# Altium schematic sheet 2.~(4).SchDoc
size 420 x 297 mm
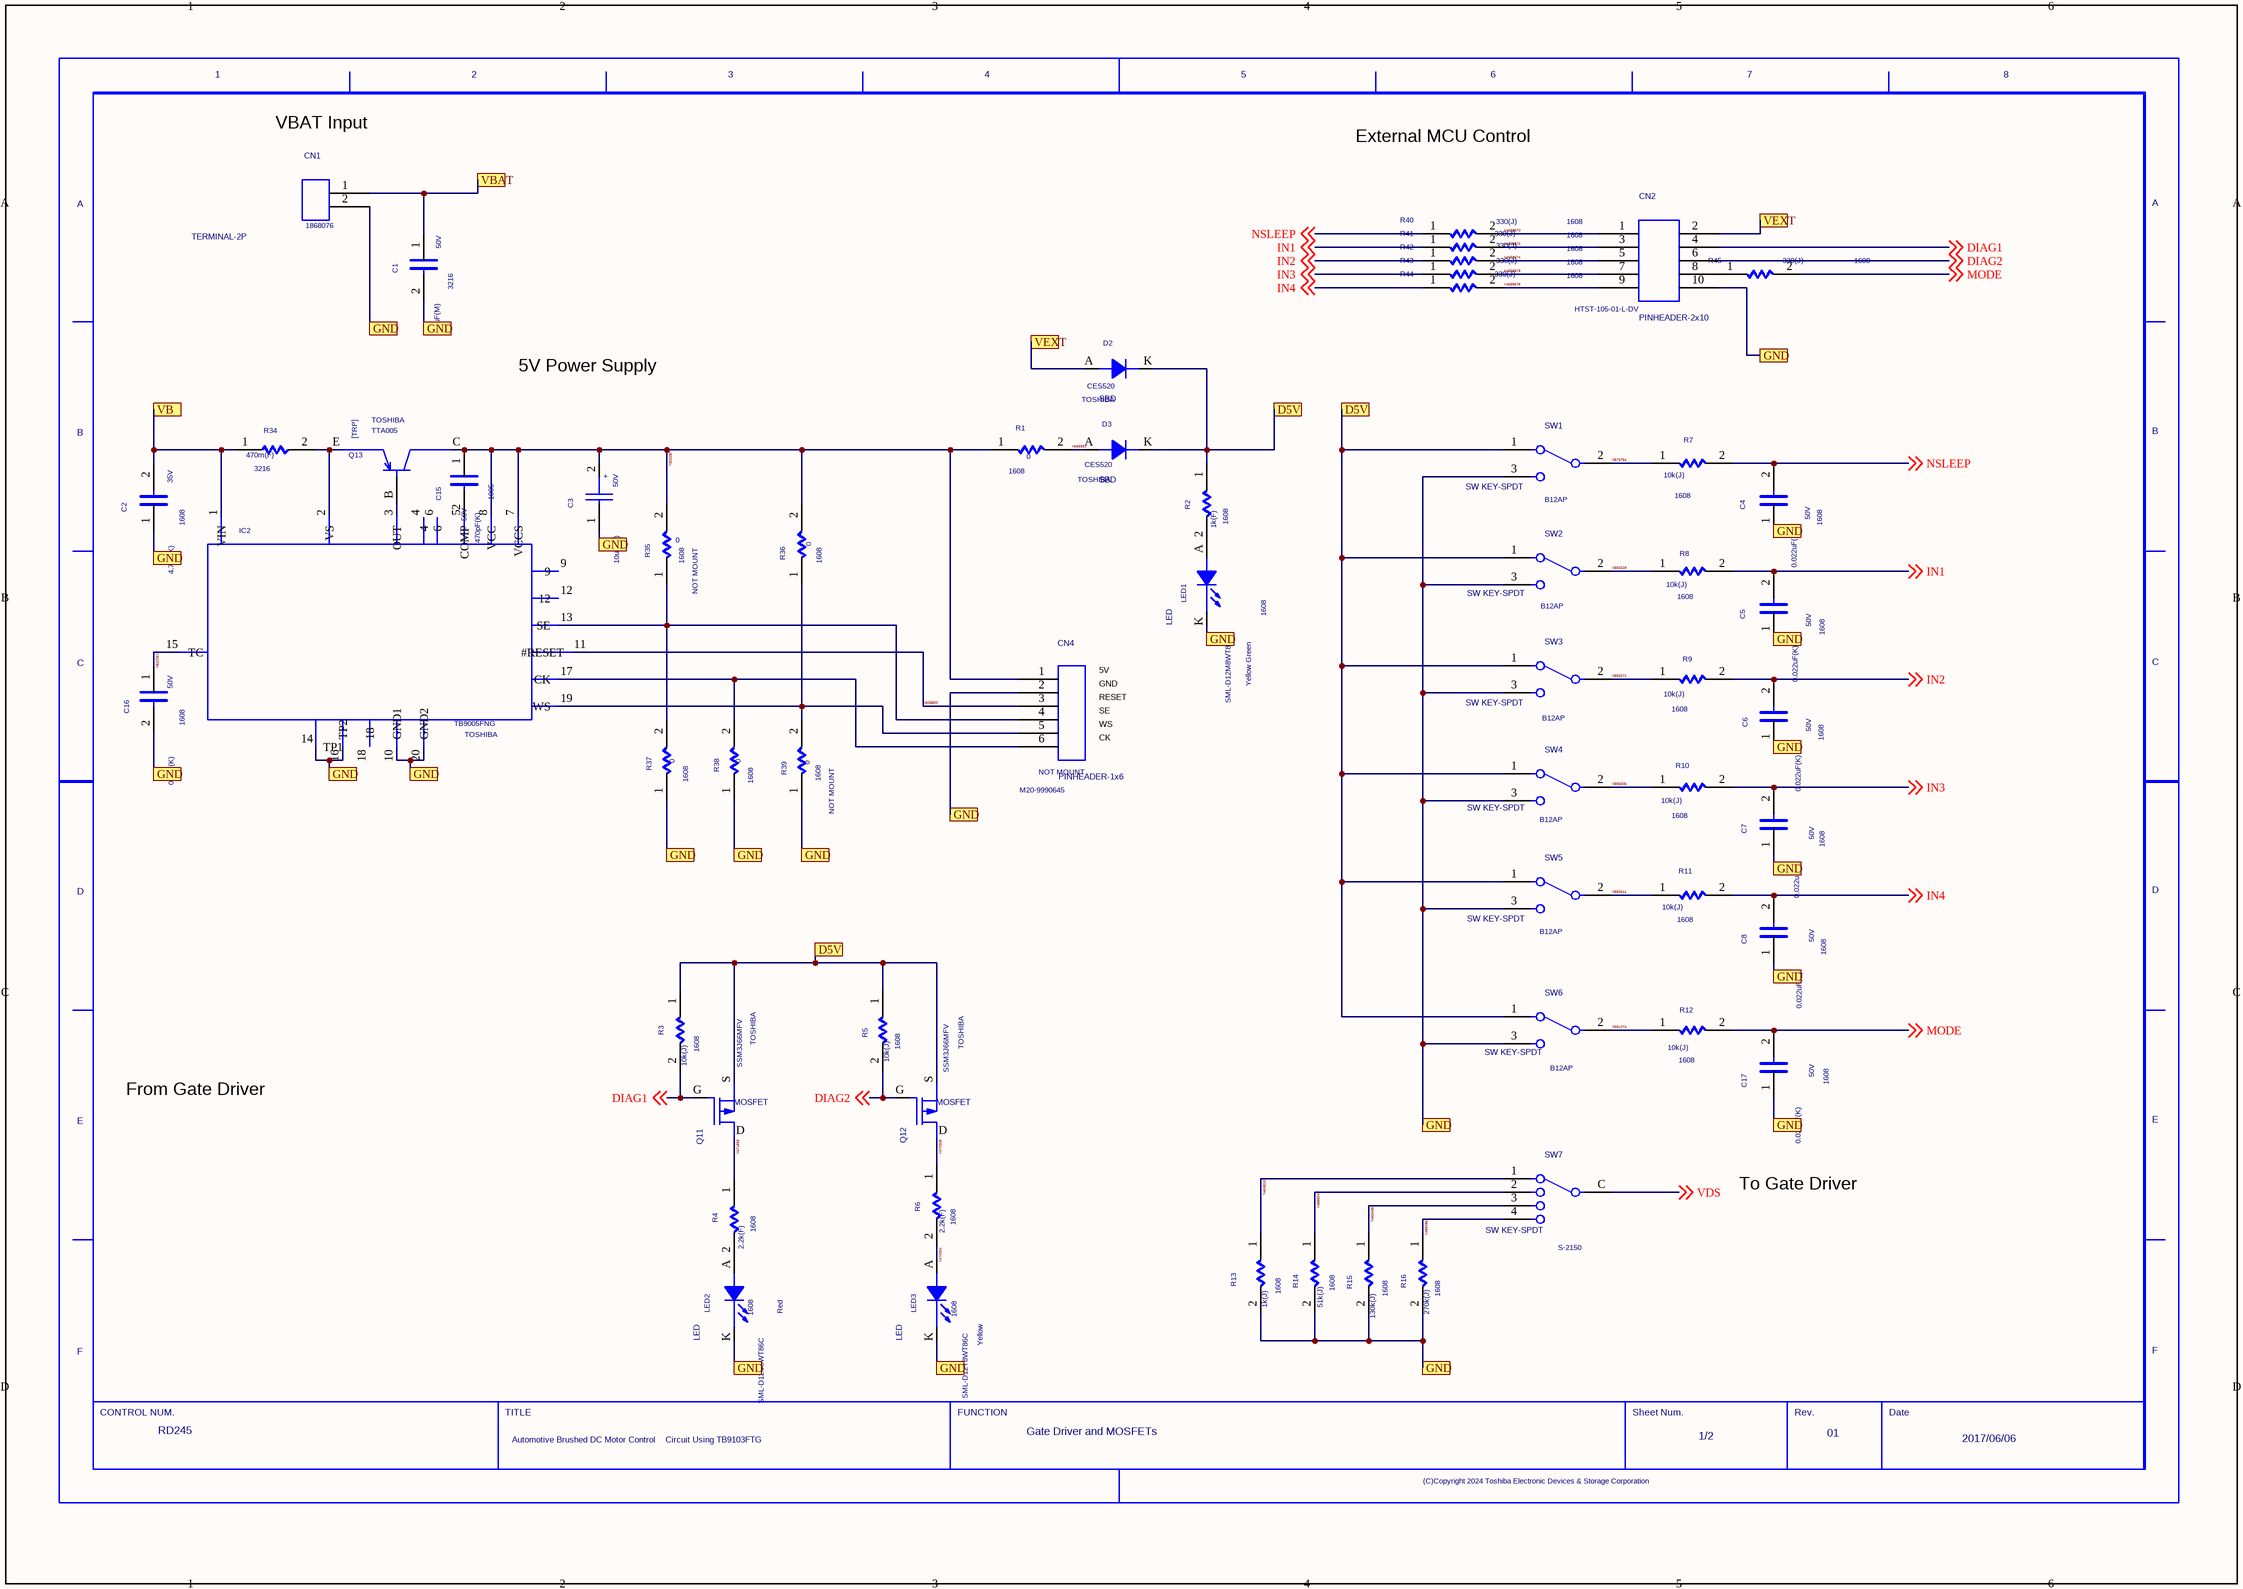
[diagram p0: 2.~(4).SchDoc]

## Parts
C1  SIZECODESMD: 3216  VAL2: 50V  VAL1: 10uF(M)  (hidden comment: C)
C2  SIZECODESMD: 1608  VAL2: 35V  VAL1: 4.7uF(K)  (hidden comment: C)
C3  VAL2: 50V  VAL1: 10uF(M)  (hidden comment: CP)
C4  SIZECODESMD: 1608  VAL2: 50V  VAL1: 0.022uF(K)  (hidden comment: C)
C5  SIZECODESMD: 1608  VAL2: 50V  VAL1: 0.022uF(K)  (hidden comment: C)
C6  SIZECODESMD: 1608  VAL2: 50V  VAL1: 0.022uF(K)  (hidden comment: C)
C7  SIZECODESMD: 1608  VAL2: 50V  VAL1: 0.022uF(K)  (hidden comment: C)
C8  SIZECODESMD: 1608  VAL2: 50V  VAL1: 0.022uF(K)  (hidden comment: C)
C15  SIZECODESMD: 1005  VAL2: 50V  VAL1: 470pF(K)  (hidden comment: C)
C16  SIZECODESMD: 1608  VAL2: 50V  VAL1: 0.1uF(K)  (hidden comment: C)
C17  SIZECODESMD: 1608  VAL2: 50V  VAL1: 0.022uF(K)  (hidden comment: C)
CN1  TERMINAL-2P  VAL3: 1868076
CN2  PINHEADER-2x10  VAL3: HTST-105-01-L-DV
CN4  PINHEADER-1x6  NOTMOUNT: NOT MOUNT  VAL3: M20-9990645
D2  SBD  USERCOMPTEXT3: TOSHIBA  VAL3: CES520
D3  SBD  USERCOMPTEXT3: TOSHIBA  VAL3: CES520
IC2  USERCOMPTEXT3: TOSHIBA  (hidden comment: TB9005FNG)
LED1  LED  SIZECODESMD: 1608  VAL3: SML-D12M8WT86C  VAL1: Yellow Green
LED2  LED  SIZECODESMD: 1608  VAL3: SML-D12U8WT86C  VAL1: Red
LED3  LED  SIZECODESMD: 1608  VAL3: SML-D12Y8WT86C  VAL1: Yellow
Q11  MOSFET  USERCOMPTEXT3: TOSHIBA  VAL3: SSM3J66MFV
Q12  MOSFET  USERCOMPTEXT3: TOSHIBA  VAL3: SSM3J66MFV
Q13  USERCOMPTEXT3: TOSHIBA  VAL3: TTA005  (hidden comment: TRP)
R1  SIZECODESMD: 1608  VAL1: 0  (hidden comment: R)
R2  SIZECODESMD: 1608  VAL1: 1k(F)  (hidden comment: R)
R3  SIZECODESMD: 1608  VAL1: 10k(J)  (hidden comment: R)
R4  SIZECODESMD: 1608  VAL1: 2.2k(F)  (hidden comment: R)
R5  SIZECODESMD: 1608  VAL1: 10k(J)  (hidden comment: R)
R6  SIZECODESMD: 1608  VAL1: 2.2k(F)  (hidden comment: R)
R7  SIZECODESMD: 1608  VAL1: 10k(J)  (hidden comment: R)
R8  SIZECODESMD: 1608  VAL1: 10k(J)  (hidden comment: R)
R9  SIZECODESMD: 1608  VAL1: 10k(J)  (hidden comment: R)
R10  SIZECODESMD: 1608  VAL1: 10k(J)  (hidden comment: R)
R11  SIZECODESMD: 1608  VAL1: 10k(J)  (hidden comment: R)
R12  SIZECODESMD: 1608  VAL1: 10k(J)  (hidden comment: R)
R13  SIZECODESMD: 1608  VAL1: 1k(J)  (hidden comment: R)
R14  SIZECODESMD: 1608  VAL1: 51k(J)  (hidden comment: R)
R15  SIZECODESMD: 1608  VAL1: 130k(J)  (hidden comment: R)
R16  SIZECODESMD: 1608  VAL1: 270k(J)  (hidden comment: R)
R34  SIZECODESMD: 3216  VAL1: 470m(F)  (hidden comment: R)
R35  SIZECODESMD: 1608  VAL1: 0  NOTMOUNT: NOT MOUNT  (hidden comment: R)
R36  SIZECODESMD: 1608  VAL1: 0  (hidden comment: R)
R37  SIZECODESMD: 1608  VAL1: 0  (hidden comment: R)
R38  SIZECODESMD: 1608  VAL1: 0  (hidden comment: R)
R39  SIZECODESMD: 1608  VAL1: 0  NOTMOUNT: NOT MOUNT  (hidden comment: R)
R40  SIZECODESMD: 1608  VAL1: 330(J)  (hidden comment: R)
R41  SIZECODESMD: 1608  VAL1: 330(J)  (hidden comment: R)
R42  SIZECODESMD: 1608  VAL1: 330(J)  (hidden comment: R)
R43  SIZECODESMD: 1608  VAL1: 330(J)  (hidden comment: R)
R44  SIZECODESMD: 1608  VAL1: 330(J)  (hidden comment: R)
R45  SIZECODESMD: 1608  VAL1: 330(J)  (hidden comment: R)
SW1  SW KEY-SPDT  VAL3: B12AP
SW2  SW KEY-SPDT  VAL3: B12AP
SW3  SW KEY-SPDT  VAL3: B12AP
SW4  SW KEY-SPDT  VAL3: B12AP
SW5  SW KEY-SPDT  VAL3: B12AP
SW6  SW KEY-SPDT  VAL3: B12AP
SW7  SW KEY-SPDT  VAL3: S-2150
U?  DATE: 2017/06/06  REVISION: 01  FUNCTION: Gate Driver and MOSFETs  DRAWINGNUMBER: RD245  TITLE: Automotive Brushed DC Motor Control / Circuit Using TB9103FTG  SHEETNUMBER: 1/2  (hidden comment: WAKU_DEF100)

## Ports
D5V, GND, VB, VBAT, VEXT

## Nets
D5V: D2.K D3.K Q11.S Q12.S R2.1 R3.1 R5.1 SW1.1(NC) SW2.1(NC) SW3.1(NC) SW4.1(NC) SW5.1(NC) SW6.1(NC) ; port D5V
DIAG1: CN2.4 Q11.G R3.2 ; off-sheet DIAG1
DIAG2: CN2.6 Q12.G R5.2 ; off-sheet DIAG2
GND: C1.2 C2.1 C3.1 C4.1 C5.1 C6.1 C7.1 C8.1 C16.2 C17.1 CN1.2 CN2.10 CN4.2 IC2.10(GND1) IC2.14(TP1) IC2.16(TP2) IC2.20(GND2) LED1.K LED2.K LED3.K R13.2 R14.2 R15.2 R16.2 R37.1 R38.1 R39.1 SW1.3(NO) SW2.3(NO) SW3.3(NO) SW4.3(NO) SW5.3(NO) SW6.3(NO) ; port GND
IN1: C5.2 R8.2 R41.1 ; off-sheet IN1
IN2: C6.2 R9.2 R42.1 ; off-sheet IN2
IN3: C7.2 R10.2 R43.1 ; off-sheet IN3
IN4: C8.2 R11.2 R44.1 ; off-sheet IN4
MODE: C17.2 R12.2 R45.2 ; off-sheet MODE
N469486: R16.1 SW7.4(NO)
N469495: R15.1 SW7.3(NO)
N469504: R14.1 SW7.2(COMMON)
N469513: R13.1 SW7.1(NC)
N470308: Q12.D R6.1
N470324: LED3.A R6.2
N471565: Q11.D R4.1
N561074: R12.1 SW6.2(COMMON)
N573754: R7.1 SW1.2(COMMON)
N593239: R8.1 SW2.2(COMMON)
N593372: R9.1 SW3.2(COMMON)
N593506: R10.1 SW4.2(COMMON)
N593641: R11.1 SW5.2(COMMON)
N622087: C3.2 C15.1 CN4.1 IC2.7(VCCS) IC2.8(VCC) Q13.C R1.1 R35.2 R36.2
N622351: C16.1 IC2.15(TC)
N628803: CN4.3 IC2.11(#RESET)
N665551: D3.A R1.2
N4658670: CN2.1 R40.2
N4658672: CN2.3 R41.2
N4658674: CN2.5 R42.2
N4658676: CN2.7 R43.2
N4658678: CN2.9 R44.2
NSLEEP: C4.2 R7.2 R40.1 ; off-sheet NSLEEP
SIG595: CN4.4 IC2.13(SE) R35.1 R37.2
SIG638: IC2.3(OUT) Q13.B
SIG639: IC2.2(VS) Q13.E R34.2
SIG642: CN4.5 IC2.19(WS) R36.1 R39.2
SIG643: CN4.6 IC2.17(CK) R38.2
VB: C2.2 IC2.1(VIN) R34.1 ; port VB
VBAT: C1.1 CN1.1 ; port VBAT
VDS: SW7.C(NO) ; off-sheet VDS
VEXT: CN2.2 D2.A ; port VEXT
NetC15_2: C15.2 IC2.5(COMP)
NetCN2_8: CN2.8 R45.1
NetLED1_A: LED1.A R2.2
NetLED2_A: LED2.A R4.2

Not connected (* = marked no-connect by the designer): IC2 4 6 9 12 18

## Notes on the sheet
- VBAT Input
- External MCU Control
- 5V Power Supply
- (near CN4) 5V
- (near CN4) GND
- (near CN4) RESET
- (near CN4) SE
- (near CN4) WS
- (near CN4) CK
- From Gate Driver
- To Gate Driver

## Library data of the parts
C1 = C: UPDATETIME: 17:22:43; UPDATEUSER: sptcae13; SAVECOUNT: 1; ORIGINALSYMBOLORIGIN: (0,0); FUNCN: C_C; VAL4: Murata; VAL3: GRT31CR61H106ME01L; CDBNAME: C0805K_2; INSTANCENAME: cmp141
C2 = C: UPDATETIME: 17:22:43; UPDATEUSER: sptcae13; SAVECOUNT: 1; ORIGINALSYMBOLORIGIN: (0,0); QUADMODEL: CON_10U; FUNCN: C_C; NOMINALCAPACITA: 10u; RATEDVOLTAGE: 25; CDMASTERCADCELG: KC0167; MAKER: TDK; OUMEMAKER: MRT 村田製作所; ADSMODELNAME: s_ZRB18AR61E106ME01L; VAL4: Murata; FNLEADFREETHET1GT2GMCTH1: N_N_N; VAL3: GRT188R6YA475KE13D; CAPACITANCETOLE: M; OUMECLASSIFICATION: セラミックコンデンサ; OUMEMAKERKATAMEI: ZRB18AR61E106ME01L; INSTANCENAME: INS669941
C3 = CP: OUMEPARTTYPE: C; SAVEAREA0: -1450,-153,20294,13055; UPDATETIME: 16:13:42; UPDATEUSER: fukuda-y; TIME: 15:02:55; SAVECOUNT: 52; ORIGINALSYMBOLORIGIN: (0,0); QUADMODEL: CON_330U; FUNCN: CP_CP; RATEDVOLTAGE: 450; NOMINALCAPACITA: 330u; CDMASTERCADCELG: DC213N; MAKER: RUBYCON; GCOUNT: 1; SIZECODESMD: DIP; OUMEMAKER: SIT ルビコン; VAL4: Chemi-Con; FNLEADFREETHET1GT2GMCTH1: 9_N_N; VAL3: HHXD500ARA100MF61G; CAPACITANCETOLE: M; OUMECLASSIFICATION: アルミ電解コンデンサ; OUMEMAKERKATAMEI: 450MXC330M35X40; CHIPSIZE: D35xL30; INSTANCENAME: INS634215
C4 = C: UPDATETIME: 17:22:43; UPDATEUSER: sptcae13; SAVECOUNT: 1; ORIGINALSYMBOLORIGIN: (0,0); QUADMODEL: CON_10U; FUNCN: C_C; NOMINALCAPACITA: 10u; RATEDVOLTAGE: 25; CDMASTERCADCELG: KC0167; MAKER: TDK; OUMEMAKER: MRT 村田製作所; ADSMODELNAME: s_ZRB18AR61E106ME01L; VAL4: Murata; FNLEADFREETHET1GT2GMCTH1: N_N_N; VAL3: GCM188R91H223KA37D; CAPACITANCETOLE: M; OUMECLASSIFICATION: セラミックコンデンサ; OUMEMAKERKATAMEI: ZRB18AR61E106ME01L; INSTANCENAME: INS573773
C5 = C: UPDATETIME: 17:22:43; UPDATEUSER: sptcae13; SAVECOUNT: 1; ORIGINALSYMBOLORIGIN: (0,0); QUADMODEL: CON_10U; FUNCN: C_C; NOMINALCAPACITA: 10u; RATEDVOLTAGE: 25; CDMASTERCADCELG: KC0167; MAKER: TDK; OUMEMAKER: MRT 村田製作所; ADSMODELNAME: s_ZRB18AR61E106ME01L; VAL4: Murata; FNLEADFREETHET1GT2GMCTH1: N_N_N; VAL3: GCM188R91H223KA37D; CAPACITANCETOLE: M; OUMECLASSIFICATION: セラミックコンデンサ; OUMEMAKERKATAMEI: ZRB18AR61E106ME01L; INSTANCENAME: INS658183
C6 = C: UPDATETIME: 17:22:43; UPDATEUSER: sptcae13; SAVECOUNT: 1; ORIGINALSYMBOLORIGIN: (0,0); QUADMODEL: CON_10U; FUNCN: C_C; NOMINALCAPACITA: 10u; RATEDVOLTAGE: 25; CDMASTERCADCELG: KC0167; MAKER: TDK; OUMEMAKER: MRT 村田製作所; ADSMODELNAME: s_ZRB18AR61E106ME01L; VAL4: Murata; FNLEADFREETHET1GT2GMCTH1: N_N_N; VAL3: GCM188R91H223KA37D; CAPACITANCETOLE: M; OUMECLASSIFICATION: セラミックコンデンサ; OUMEMAKERKATAMEI: ZRB18AR61E106ME01L; INSTANCENAME: INS658285
C7 = C: UPDATETIME: 17:22:43; UPDATEUSER: sptcae13; SAVECOUNT: 1; ORIGINALSYMBOLORIGIN: (0,0); QUADMODEL: CON_10U; FUNCN: C_C; NOMINALCAPACITA: 10u; RATEDVOLTAGE: 25; CDMASTERCADCELG: KC0167; MAKER: TDK; OUMEMAKER: MRT 村田製作所; ADSMODELNAME: s_ZRB18AR61E106ME01L; VAL4: Murata; FNLEADFREETHET1GT2GMCTH1: N_N_N; VAL3: GCM188R91H223KA37D; CAPACITANCETOLE: M; OUMECLASSIFICATION: セラミックコンデンサ; OUMEMAKERKATAMEI: ZRB18AR61E106ME01L; INSTANCENAME: INS658387
C8 = C: UPDATETIME: 17:22:43; UPDATEUSER: sptcae13; SAVECOUNT: 1; ORIGINALSYMBOLORIGIN: (0,0); QUADMODEL: CON_10U; FUNCN: C_C; NOMINALCAPACITA: 10u; RATEDVOLTAGE: 25; CDMASTERCADCELG: KC0167; MAKER: TDK; OUMEMAKER: MRT 村田製作所; ADSMODELNAME: s_ZRB18AR61E106ME01L; VAL4: Murata; FNLEADFREETHET1GT2GMCTH1: N_N_N; VAL3: GCM188R91H223KA37D; CAPACITANCETOLE: M; OUMECLASSIFICATION: セラミックコンデンサ; OUMEMAKERKATAMEI: ZRB18AR61E106ME01L; INSTANCENAME: INS658489
C15 = C: UPDATETIME: 17:22:43; UPDATEUSER: sptcae13; SAVECOUNT: 1; ORIGINALSYMBOLORIGIN: (0,0); FUNCN: C_C; VAL4: Murata; VAL3: GCM155R71H471KA37J; CDBNAME: C0805K_2; INSTANCENAME: cmp141
C16 = C: UPDATETIME: 17:22:43; UPDATEUSER: sptcae13; SAVECOUNT: 1; ORIGINALSYMBOLORIGIN: (0,0); FUNCN: C_C; VAL4: Murata; VAL3: GCM188R71H104KA57J; CDBNAME: C0805K_3; INSTANCENAME: cmp152
C17 = C: UPDATETIME: 17:22:43; UPDATEUSER: sptcae13; SAVECOUNT: 1; ORIGINALSYMBOLORIGIN: (0,0); QUADMODEL: CON_10U; FUNCN: C_C; NOMINALCAPACITA: 10u; RATEDVOLTAGE: 25; CDMASTERCADCELG: KC0167; MAKER: TDK; OUMEMAKER: MRT 村田製作所; ADSMODELNAME: s_ZRB18AR61E106ME01L; VAL4: Murata; FNLEADFREETHET1GT2GMCTH1: N_N_N; VAL3: GCM188R91H223KA37D; CAPACITANCETOLE: M; OUMECLASSIFICATION: セラミックコンデンサ; OUMEMAKERKATAMEI: ZRB18AR61E106ME01L; INSTANCENAME: INS658591
CN1 = CON2: SAVECOUNT: 1; UPDATEUSER: sptcae13; UPDATETIME: 09:49:24; OriginalSymbolOrigin: (0,0); FUNCN: CON2_CON2; VAL4: Phoenix; VAL2: 500V/32A; INSTANCENAME: INS451962
CN2 = CON10A: SAVECOUNT: 1; UPDATEUSER: sptcae13; UPDATETIME: 09:49:24; OriginalSymbolOrigin: (0,0); FUNCN: CON10A_CON10A; VAL4: Samtec; INSTANCENAME: INS465841
CN4 = CON6: SAVECOUNT: 1; UPDATEUSER: sptcae13; UPDATETIME: 09:49:24; OriginalSymbolOrigin: (0,0); FUNCN: CON6_CON6; VAL4: Harwin; INSTANCENAME: INS655764
D2 = DIODE_0: SAVECOUNT: 1; UPDATEUSER: sptcae13; UPDATETIME: 09:49:24; OriginalSymbolOrigin: (0,0); FUNCN: DIODE_0_DIODE_0; INSTANCENAME: INS572955
D3 = DIODE_0: SAVECOUNT: 1; UPDATEUSER: sptcae13; UPDATETIME: 09:49:24; OriginalSymbolOrigin: (0,0); FUNCN: DIODE_0_DIODE_0; INSTANCENAME: INS573569
IC2 = TB9005FNG_1: SAVEAREA0: -26622,-27385,86055,19754; UPDATETIME: 09:48:39; UPDATEUSER: sptcae13; TIME: 17:22:42; SAVECOUNT: 3; ORIGINALSYMBOLORIGIN: (-5080,5080); FUNCN: TB9005FNG_1_TB9005FNG_1; VAL1: LINEAR IC; INSTANCENAME: INS622199
LED1 = LED_2: SAVECOUNT: 1; UPDATEUSER: sptcae13; UPDATETIME: 09:49:24; OriginalSymbolOrigin: (0,0); FUNCN: LED_2_LED_2; VAL4: Rohm; INSTANCENAME: INS453112
LED2 = LED_2: SAVECOUNT: 1; UPDATEUSER: sptcae13; UPDATETIME: 09:49:24; OriginalSymbolOrigin: (0,0); FUNCN: LED_2_LED_2; VAL4: Rohm; INSTANCENAME: INS496113
LED3 = LED_2: SAVECOUNT: 1; UPDATEUSER: sptcae13; UPDATETIME: 09:49:24; OriginalSymbolOrigin: (0,0); FUNCN: LED_2_LED_2; VAL4: Rohm; INSTANCENAME: INS496225
Q11 = ZVP0545_TO_0: SAVECOUNT: 1; UPDATEUSER: sptcae13; UPDATETIME: 09:49:23; OriginalSymbolOrigin: (0,5080); FUNCN: ZVP0545_TO_0_ZVP0545_TO_0; INSTANCENAME: INS493920
Q12 = ZVP0545_TO_0: SAVECOUNT: 1; UPDATEUSER: sptcae13; UPDATETIME: 09:49:23; OriginalSymbolOrigin: (0,5080); FUNCN: ZVP0545_TO_0_ZVP0545_TO_0; INSTANCENAME: INS494083
Q13 = TRP: SAVEAREA0: -5466,-244,29263,20886; UPDATETIME: 17:22:43; UPDATEUSER: sptcae13; SAVECOUNT: 1; ORIGINALSYMBOLORIGIN: (0,0); FUNCN: TRP_TRP; INSTANCENAME: cmp138
R1 = R: UPDATETIME: 17:22:43; UPDATEUSER: sptcae13; SAVECOUNT: 1; ORIGINALSYMBOLORIGIN: (0,0); QUADMODEL: RES_1M; FUNCN: R_R; CDMASTERCADCELG: KC0020; MAKER: KOA; RESISTANCETOLER: J; OUMEMAKER: SSM 進工業; POWERRATING: 500m; MOUNTINGFORMSMD: SMD; NOMINALRESISTAN: 1m; ADSMODELNAME: s_RL1632H_R001_JN; FNLEADFREETHET1GT2GMCTH1: N_N_N; VAL3: RK73Z1JTTD; OUMECLASSIFICATION: 表面実装用固定抵抗器; OUMEMAKERKATAMEI: RL1632H-R001-JN; CHIPSIZE: 3216; INSTANCENAME: INS575096
R2 = R: UPDATETIME: 17:22:43; UPDATEUSER: sptcae13; SAVECOUNT: 1; ORIGINALSYMBOLORIGIN: (0,0); QUADMODEL: RES_1M; FUNCN: R_R; CDMASTERCADCELG: KC0020; MAKER: KOA; RESISTANCETOLER: J; OUMEMAKER: SSM 進工業; POWERRATING: 500m; MOUNTINGFORMSMD: SMD; NOMINALRESISTAN: 1m; ADSMODELNAME: s_RL1632H_R001_JN; FNLEADFREETHET1GT2GMCTH1: N_N_N; VAL3: RK73H1JTTD1001F; VAL2: 125mW; OUMECLASSIFICATION: 表面実装用固定抵抗器; OUMEMAKERKATAMEI: RL1632H-R001-JN; CHIPSIZE: 3216; INSTANCENAME: INS454341
R3 = R: UPDATETIME: 17:22:43; UPDATEUSER: sptcae13; SAVECOUNT: 1; ORIGINALSYMBOLORIGIN: (0,0); QUADMODEL: RES_1M; FUNCN: R_R; CDMASTERCADCELG: KC0020; MAKER: KOA; RESISTANCETOLER: J; OUMEMAKER: SSM 進工業; POWERRATING: 500m; MOUNTINGFORMSMD: SMD; NOMINALRESISTAN: 1m; ADSMODELNAME: s_RL1632H_R001_JN; FNLEADFREETHET1GT2GMCTH1: N_N_N; VAL3: RK73B1JTTD103J; VAL2: 100mW; OUMECLASSIFICATION: 表面実装用固定抵抗器; OUMEMAKERKATAMEI: RL1632H-R001-JN; CHIPSIZE: 3216; INSTANCENAME: INS486568
R4 = R: UPDATETIME: 17:22:43; UPDATEUSER: sptcae13; SAVECOUNT: 1; ORIGINALSYMBOLORIGIN: (0,0); QUADMODEL: RES_1M; FUNCN: R_R; CDMASTERCADCELG: KC0020; MAKER: KOA; RESISTANCETOLER: J; OUMEMAKER: SSM 進工業; POWERRATING: 500m; MOUNTINGFORMSMD: SMD; NOMINALRESISTAN: 1m; ADSMODELNAME: s_RL1632H_R001_JN; FNLEADFREETHET1GT2GMCTH1: N_N_N; VAL3: RK73H1JTTD2201F; VAL2: 100mW; OUMECLASSIFICATION: 表面実装用固定抵抗器; OUMEMAKERKATAMEI: RL1632H-R001-JN; CHIPSIZE: 3216; INSTANCENAME: INS471567
R5 = R: UPDATETIME: 17:22:43; UPDATEUSER: sptcae13; SAVECOUNT: 1; ORIGINALSYMBOLORIGIN: (0,0); QUADMODEL: RES_1M; FUNCN: R_R; CDMASTERCADCELG: KC0020; MAKER: KOA; RESISTANCETOLER: J; OUMEMAKER: SSM 進工業; POWERRATING: 500m; MOUNTINGFORMSMD: SMD; NOMINALRESISTAN: 1m; ADSMODELNAME: s_RL1632H_R001_JN; FNLEADFREETHET1GT2GMCTH1: N_N_N; VAL3: RK73B1JTTD103J; VAL2: 100mW; OUMECLASSIFICATION: 表面実装用固定抵抗器; OUMEMAKERKATAMEI: RL1632H-R001-JN; CHIPSIZE: 3216; INSTANCENAME: INS487189
R6 = R: UPDATETIME: 17:22:43; UPDATEUSER: sptcae13; SAVECOUNT: 1; ORIGINALSYMBOLORIGIN: (0,0); QUADMODEL: RES_1M; FUNCN: R_R; CDMASTERCADCELG: KC0020; MAKER: KOA; RESISTANCETOLER: J; OUMEMAKER: SSM 進工業; POWERRATING: 500m; MOUNTINGFORMSMD: SMD; NOMINALRESISTAN: 1m; ADSMODELNAME: s_RL1632H_R001_JN; FNLEADFREETHET1GT2GMCTH1: N_N_N; VAL3: RK73H1JTTD2201F; VAL2: 100mW; OUMECLASSIFICATION: 表面実装用固定抵抗器; OUMEMAKERKATAMEI: RL1632H-R001-JN; CHIPSIZE: 3216; INSTANCENAME: INS470310
R7 = R: UPDATETIME: 17:22:43; UPDATEUSER: sptcae13; SAVECOUNT: 1; ORIGINALSYMBOLORIGIN: (0,0); QUADMODEL: RES_1M; FUNCN: R_R; CDMASTERCADCELG: KC0020; MAKER: KOA; RESISTANCETOLER: J; OUMEMAKER: SSM 進工業; POWERRATING: 500m; MOUNTINGFORMSMD: SMD; NOMINALRESISTAN: 1m; ADSMODELNAME: s_RL1632H_R001_JN; FNLEADFREETHET1GT2GMCTH1: N_N_N; VAL3: RK73B1JTTD103J; VAL2: 100mW; OUMECLASSIFICATION: 表面実装用固定抵抗器; OUMEMAKERKATAMEI: RL1632H-R001-JN; CHIPSIZE: 3216; INSTANCENAME: INS515728
R8 = R: UPDATETIME: 17:22:43; UPDATEUSER: sptcae13; SAVECOUNT: 1; ORIGINALSYMBOLORIGIN: (0,0); QUADMODEL: RES_1M; FUNCN: R_R; CDMASTERCADCELG: KC0020; MAKER: KOA; RESISTANCETOLER: J; OUMEMAKER: SSM 進工業; POWERRATING: 500m; MOUNTINGFORMSMD: SMD; NOMINALRESISTAN: 1m; ADSMODELNAME: s_RL1632H_R001_JN; FNLEADFREETHET1GT2GMCTH1: N_N_N; VAL3: RK73B1JTTD103J; VAL2: 100mW; OUMECLASSIFICATION: 表面実装用固定抵抗器; OUMEMAKERKATAMEI: RL1632H-R001-JN; CHIPSIZE: 3216; INSTANCENAME: INS593225
R9 = R: UPDATETIME: 17:22:43; UPDATEUSER: sptcae13; SAVECOUNT: 1; ORIGINALSYMBOLORIGIN: (0,0); QUADMODEL: RES_1M; FUNCN: R_R; CDMASTERCADCELG: KC0020; MAKER: KOA; RESISTANCETOLER: J; OUMEMAKER: SSM 進工業; POWERRATING: 500m; MOUNTINGFORMSMD: SMD; NOMINALRESISTAN: 1m; ADSMODELNAME: s_RL1632H_R001_JN; FNLEADFREETHET1GT2GMCTH1: N_N_N; VAL3: RK73B1JTTD103J; VAL2: 100mW; OUMECLASSIFICATION: 表面実装用固定抵抗器; OUMEMAKERKATAMEI: RL1632H-R001-JN; CHIPSIZE: 3216; INSTANCENAME: INS593358
R10 = R: UPDATETIME: 17:22:43; UPDATEUSER: sptcae13; SAVECOUNT: 1; ORIGINALSYMBOLORIGIN: (0,0); QUADMODEL: RES_1M; FUNCN: R_R; CDMASTERCADCELG: KC0020; MAKER: KOA; RESISTANCETOLER: J; OUMEMAKER: SSM 進工業; POWERRATING: 500m; MOUNTINGFORMSMD: SMD; NOMINALRESISTAN: 1m; ADSMODELNAME: s_RL1632H_R001_JN; FNLEADFREETHET1GT2GMCTH1: N_N_N; VAL3: RK73B1JTTD103J; VAL2: 100mW; OUMECLASSIFICATION: 表面実装用固定抵抗器; OUMEMAKERKATAMEI: RL1632H-R001-JN; CHIPSIZE: 3216; INSTANCENAME: INS593492
R11 = R: UPDATETIME: 17:22:43; UPDATEUSER: sptcae13; SAVECOUNT: 1; ORIGINALSYMBOLORIGIN: (0,0); QUADMODEL: RES_1M; FUNCN: R_R; CDMASTERCADCELG: KC0020; MAKER: KOA; RESISTANCETOLER: J; OUMEMAKER: SSM 進工業; POWERRATING: 500m; MOUNTINGFORMSMD: SMD; NOMINALRESISTAN: 1m; ADSMODELNAME: s_RL1632H_R001_JN; FNLEADFREETHET1GT2GMCTH1: N_N_N; VAL3: RK73B1JTTD103J; VAL2: 100mW; OUMECLASSIFICATION: 表面実装用固定抵抗器; OUMEMAKERKATAMEI: RL1632H-R001-JN; CHIPSIZE: 3216; INSTANCENAME: INS593627
R12 = R: UPDATETIME: 17:22:43; UPDATEUSER: sptcae13; SAVECOUNT: 1; ORIGINALSYMBOLORIGIN: (0,0); QUADMODEL: RES_1M; FUNCN: R_R; CDMASTERCADCELG: KC0020; MAKER: KOA; RESISTANCETOLER: J; OUMEMAKER: SSM 進工業; POWERRATING: 500m; MOUNTINGFORMSMD: SMD; NOMINALRESISTAN: 1m; ADSMODELNAME: s_RL1632H_R001_JN; FNLEADFREETHET1GT2GMCTH1: N_N_N; VAL3: RK73B1JTTD103J; VAL2: 100mW; OUMECLASSIFICATION: 表面実装用固定抵抗器; OUMEMAKERKATAMEI: RL1632H-R001-JN; CHIPSIZE: 3216; INSTANCENAME: INS561051
R13 = R: UPDATETIME: 17:22:43; UPDATEUSER: sptcae13; SAVECOUNT: 1; ORIGINALSYMBOLORIGIN: (0,0); QUADMODEL: RES_1M; FUNCN: R_R; CDMASTERCADCELG: KC0020; MAKER: KOA; RESISTANCETOLER: J; OUMEMAKER: SSM 進工業; POWERRATING: 500m; MOUNTINGFORMSMD: SMD; NOMINALRESISTAN: 1m; ADSMODELNAME: s_RL1632H_R001_JN; FNLEADFREETHET1GT2GMCTH1: N_N_N; VAL3: RK73B1JTTD102J; VAL2: 125mW; OUMECLASSIFICATION: 表面実装用固定抵抗器; OUMEMAKERKATAMEI: RL1632H-R001-JN; CHIPSIZE: 3216; INSTANCENAME: INS467908
R14 = R: UPDATETIME: 17:22:43; UPDATEUSER: sptcae13; SAVECOUNT: 1; ORIGINALSYMBOLORIGIN: (0,0); QUADMODEL: RES_1M; FUNCN: R_R; CDMASTERCADCELG: KC0020; MAKER: KOA; RESISTANCETOLER: J; OUMEMAKER: SSM 進工業; POWERRATING: 500m; MOUNTINGFORMSMD: SMD; NOMINALRESISTAN: 1m; ADSMODELNAME: s_RL1632H_R001_JN; FNLEADFREETHET1GT2GMCTH1: N_N_N; VAL3: RK73B1JTTD513J; VAL2: 100mW; OUMECLASSIFICATION: 表面実装用固定抵抗器; OUMEMAKERKATAMEI: RL1632H-R001-JN; CHIPSIZE: 3216; INSTANCENAME: INS467930
R15 = R: UPDATETIME: 17:22:43; UPDATEUSER: sptcae13; SAVECOUNT: 1; ORIGINALSYMBOLORIGIN: (0,0); QUADMODEL: RES_1M; FUNCN: R_R; CDMASTERCADCELG: KC0020; MAKER: KOA; RESISTANCETOLER: J; OUMEMAKER: SSM 進工業; POWERRATING: 500m; MOUNTINGFORMSMD: SMD; NOMINALRESISTAN: 1m; ADSMODELNAME: s_RL1632H_R001_JN; FNLEADFREETHET1GT2GMCTH1: N_N_N; VAL3: RK73B1JTTD134J; VAL2: 100mW; OUMECLASSIFICATION: 表面実装用固定抵抗器; OUMEMAKERKATAMEI: RL1632H-R001-JN; CHIPSIZE: 3216; INSTANCENAME: INS467952
R16 = R: UPDATETIME: 17:22:43; UPDATEUSER: sptcae13; SAVECOUNT: 1; ORIGINALSYMBOLORIGIN: (0,0); QUADMODEL: RES_1M; FUNCN: R_R; CDMASTERCADCELG: KC0020; MAKER: KOA; RESISTANCETOLER: J; OUMEMAKER: SSM 進工業; POWERRATING: 500m; MOUNTINGFORMSMD: SMD; NOMINALRESISTAN: 1m; ADSMODELNAME: s_RL1632H_R001_JN; FNLEADFREETHET1GT2GMCTH1: N_N_N; VAL3: RK73B1JTTD274J; VAL2: 100mW; OUMECLASSIFICATION: 表面実装用固定抵抗器; OUMEMAKERKATAMEI: RL1632H-R001-JN; CHIPSIZE: 3216; INSTANCENAME: INS467974
R34 = R: UPDATETIME: 17:22:43; UPDATEUSER: sptcae13; SAVECOUNT: 1; ORIGINALSYMBOLORIGIN: (0,0); FUNCN: R_R; VAL4: Panasonic; VAL3: ERJ8BQFR47V; VAL2: 0.5W; CDBNAME: R1206; INSTANCENAME: cmp140
R35 = R: UPDATETIME: 17:22:43; UPDATEUSER: sptcae13; SAVECOUNT: 1; ORIGINALSYMBOLORIGIN: (0,0); QUADMODEL: RES_1M; FUNCN: R_R; CDMASTERCADCELG: KC0020; MAKER: KOA; RESISTANCETOLER: J; OUMEMAKER: SSM 進工業; POWERRATING: 500m; MOUNTINGFORMSMD: SMD; NOMINALRESISTAN: 1m; ADSMODELNAME: s_RL1632H_R001_JN; FNLEADFREETHET1GT2GMCTH1: N_N_N; VAL3: RK73Z1JTTD; OUMECLASSIFICATION: 表面実装用固定抵抗器; OUMEMAKERKATAMEI: RL1632H-R001-JN; CHIPSIZE: 3216; INSTANCENAME: INS628941
R36 = R: UPDATETIME: 17:22:43; UPDATEUSER: sptcae13; SAVECOUNT: 1; ORIGINALSYMBOLORIGIN: (0,0); QUADMODEL: RES_1M; FUNCN: R_R; CDMASTERCADCELG: KC0020; MAKER: KOA; RESISTANCETOLER: J; OUMEMAKER: SSM 進工業; POWERRATING: 500m; MOUNTINGFORMSMD: SMD; NOMINALRESISTAN: 1m; ADSMODELNAME: s_RL1632H_R001_JN; FNLEADFREETHET1GT2GMCTH1: N_N_N; VAL3: RK73Z1JTTD; OUMECLASSIFICATION: 表面実装用固定抵抗器; OUMEMAKERKATAMEI: RL1632H-R001-JN; CHIPSIZE: 3216; INSTANCENAME: INS628993
R37 = R: UPDATETIME: 17:22:43; UPDATEUSER: sptcae13; SAVECOUNT: 1; ORIGINALSYMBOLORIGIN: (0,0); QUADMODEL: RES_1M; FUNCN: R_R; CDMASTERCADCELG: KC0020; MAKER: KOA; RESISTANCETOLER: J; OUMEMAKER: SSM 進工業; POWERRATING: 500m; MOUNTINGFORMSMD: SMD; NOMINALRESISTAN: 1m; ADSMODELNAME: s_RL1632H_R001_JN; FNLEADFREETHET1GT2GMCTH1: N_N_N; VAL3: RK73Z1JTTD; OUMECLASSIFICATION: 表面実装用固定抵抗器; OUMEMAKERKATAMEI: RL1632H-R001-JN; CHIPSIZE: 3216; INSTANCENAME: INS629194
R38 = R: UPDATETIME: 17:22:43; UPDATEUSER: sptcae13; SAVECOUNT: 1; ORIGINALSYMBOLORIGIN: (0,0); QUADMODEL: RES_1M; FUNCN: R_R; CDMASTERCADCELG: KC0020; MAKER: KOA; RESISTANCETOLER: J; OUMEMAKER: SSM 進工業; POWERRATING: 500m; MOUNTINGFORMSMD: SMD; NOMINALRESISTAN: 1m; ADSMODELNAME: s_RL1632H_R001_JN; FNLEADFREETHET1GT2GMCTH1: N_N_N; VAL3: RK73Z1JTTD; OUMECLASSIFICATION: 表面実装用固定抵抗器; OUMEMAKERKATAMEI: RL1632H-R001-JN; CHIPSIZE: 3216; INSTANCENAME: INS629216
R39 = R: UPDATETIME: 17:22:43; UPDATEUSER: sptcae13; SAVECOUNT: 1; ORIGINALSYMBOLORIGIN: (0,0); QUADMODEL: RES_1M; FUNCN: R_R; CDMASTERCADCELG: KC0020; MAKER: KOA; RESISTANCETOLER: J; OUMEMAKER: SSM 進工業; POWERRATING: 500m; MOUNTINGFORMSMD: SMD; NOMINALRESISTAN: 1m; ADSMODELNAME: s_RL1632H_R001_JN; FNLEADFREETHET1GT2GMCTH1: N_N_N; VAL3: RK73Z1JTTD; OUMECLASSIFICATION: 表面実装用固定抵抗器; OUMEMAKERKATAMEI: RL1632H-R001-JN; CHIPSIZE: 3216; INSTANCENAME: INS634861
R40 = R_0: SAVECOUNT: 1; UPDATEUSER: sptcae13; UPDATETIME: 09:49:24; ORIGINALSYMBOLORIGIN: (0,0); QUADMODEL: RES_1M; FUNCN: R_0_R_0; CDMASTERCADCELG: KC0020; MAKER: KOA; RESISTANCETOLER: J; OUMEMAKER: SSM 進工業; POWERRATING: 500m; MOUNTINGFORMSMD: SMD; NOMINALRESISTAN: 1m; ADSMODELNAME: s_RL1632H_R001_JN; FNLEADFREETHET1GT2GMCTH1: N_N_N; VAL3: RK73B1JTTD331J; VAL2: 125mW; OUMECLASSIFICATION: 表面実装用固定抵抗器; OUMEMAKERKATAMEI: RL1632H-R001-JN; CHIPSIZE: 3216; INSTANCENAME: INS642505
R41 = R_0: SAVECOUNT: 1; UPDATEUSER: sptcae13; UPDATETIME: 09:49:24; ORIGINALSYMBOLORIGIN: (0,0); QUADMODEL: RES_1M; FUNCN: R_0_R_0; CDMASTERCADCELG: KC0020; MAKER: KOA; RESISTANCETOLER: J; OUMEMAKER: SSM 進工業; POWERRATING: 500m; MOUNTINGFORMSMD: SMD; NOMINALRESISTAN: 1m; ADSMODELNAME: s_RL1632H_R001_JN; FNLEADFREETHET1GT2GMCTH1: N_N_N; VAL3: RK73B1JTTD331J; VAL2: 125mW; OUMECLASSIFICATION: 表面実装用固定抵抗器; OUMEMAKERKATAMEI: RL1632H-R001-JN; CHIPSIZE: 3216; INSTANCENAME: INS642429
R42 = R_0: SAVECOUNT: 1; UPDATEUSER: sptcae13; UPDATETIME: 09:49:24; ORIGINALSYMBOLORIGIN: (0,0); QUADMODEL: RES_1M; FUNCN: R_0_R_0; CDMASTERCADCELG: KC0020; MAKER: KOA; RESISTANCETOLER: J; OUMEMAKER: SSM 進工業; POWERRATING: 500m; MOUNTINGFORMSMD: SMD; NOMINALRESISTAN: 1m; ADSMODELNAME: s_RL1632H_R001_JN; FNLEADFREETHET1GT2GMCTH1: N_N_N; VAL3: RK73B1JTTD331J; VAL2: 125mW; OUMECLASSIFICATION: 表面実装用固定抵抗器; OUMEMAKERKATAMEI: RL1632H-R001-JN; CHIPSIZE: 3216; INSTANCENAME: INS642303
R43 = R_0: SAVECOUNT: 1; UPDATEUSER: sptcae13; UPDATETIME: 09:49:24; ORIGINALSYMBOLORIGIN: (0,0); QUADMODEL: RES_1M; FUNCN: R_0_R_0; CDMASTERCADCELG: KC0020; MAKER: KOA; RESISTANCETOLER: J; OUMEMAKER: SSM 進工業; POWERRATING: 500m; MOUNTINGFORMSMD: SMD; NOMINALRESISTAN: 1m; ADSMODELNAME: s_RL1632H_R001_JN; FNLEADFREETHET1GT2GMCTH1: N_N_N; VAL3: RK73B1JTTD331J; VAL2: 125mW; OUMECLASSIFICATION: 表面実装用固定抵抗器; OUMEMAKERKATAMEI: RL1632H-R001-JN; CHIPSIZE: 3216; INSTANCENAME: INS642261
R44 = R_0: SAVECOUNT: 1; UPDATEUSER: sptcae13; UPDATETIME: 09:49:24; ORIGINALSYMBOLORIGIN: (0,0); QUADMODEL: RES_1M; FUNCN: R_0_R_0; CDMASTERCADCELG: KC0020; MAKER: KOA; RESISTANCETOLER: J; OUMEMAKER: SSM 進工業; POWERRATING: 500m; MOUNTINGFORMSMD: SMD; NOMINALRESISTAN: 1m; ADSMODELNAME: s_RL1632H_R001_JN; FNLEADFREETHET1GT2GMCTH1: N_N_N; VAL3: RK73B1JTTD331J; VAL2: 125mW; OUMECLASSIFICATION: 表面実装用固定抵抗器; OUMEMAKERKATAMEI: RL1632H-R001-JN; CHIPSIZE: 3216; INSTANCENAME: INS642387
R45 = R_0: SAVECOUNT: 1; UPDATEUSER: sptcae13; UPDATETIME: 09:49:24; ORIGINALSYMBOLORIGIN: (0,0); QUADMODEL: RES_1M; FUNCN: R_0_R_0; CDMASTERCADCELG: KC0020; MAKER: KOA; RESISTANCETOLER: J; OUMEMAKER: SSM 進工業; POWERRATING: 500m; MOUNTINGFORMSMD: SMD; NOMINALRESISTAN: 1m; ADSMODELNAME: s_RL1632H_R001_JN; FNLEADFREETHET1GT2GMCTH1: N_N_N; VAL3: RK73B1JTTD331J; VAL2: 125mW; OUMECLASSIFICATION: 表面実装用固定抵抗器; OUMEMAKERKATAMEI: RL1632H-R001-JN; CHIPSIZE: 3216; INSTANCENAME: INS642773
SW1 = 154ANS_0: SAVECOUNT: 1; UPDATEUSER: sptcae13; UPDATETIME: 09:49:24; OriginalSymbolOrigin: (-2540,0); FUNCN: 154ANS_0_154ANS_0; VAL4: NKK; VAL2: 28VDC/0.4VA; INSTANCENAME: INS614366
SW2 = 154ANS_0: SAVECOUNT: 1; UPDATEUSER: sptcae13; UPDATETIME: 09:49:24; OriginalSymbolOrigin: (-2540,0); FUNCN: 154ANS_0_154ANS_0; VAL4: NKK; VAL2: 28VDC/0.4VA; INSTANCENAME: INS473874
SW3 = 154ANS_0: SAVECOUNT: 1; UPDATEUSER: sptcae13; UPDATETIME: 09:49:24; OriginalSymbolOrigin: (-2540,0); FUNCN: 154ANS_0_154ANS_0; VAL4: NKK; VAL2: 28VDC/0.4VA; INSTANCENAME: INS614843
SW4 = 154ANS_0: SAVECOUNT: 1; UPDATEUSER: sptcae13; UPDATETIME: 09:49:24; OriginalSymbolOrigin: (-2540,0); FUNCN: 154ANS_0_154ANS_0; VAL4: NKK; VAL2: 28VDC/0.4VA; INSTANCENAME: INS614962
SW5 = 154ANS_0: SAVECOUNT: 1; UPDATEUSER: sptcae13; UPDATETIME: 09:49:24; OriginalSymbolOrigin: (-2540,0); FUNCN: 154ANS_0_154ANS_0; VAL4: NKK; VAL2: 28VDC/0.4VA; INSTANCENAME: INS615081
SW6 = 154ANS_0: SAVECOUNT: 1; UPDATEUSER: sptcae13; UPDATETIME: 09:49:24; OriginalSymbolOrigin: (-2540,0); FUNCN: 154ANS_0_154ANS_0; VAL4: NKK; VAL2: 28VDC/0.4VA; INSTANCENAME: INS615857
SW7 = 154ANS_2: SAVECOUNT: 1; UPDATEUSER: sptcae13; UPDATETIME: 09:49:24; OriginalSymbolOrigin: (-2540,0); FUNCN: 154ANS_2_154ANS_2; VAL4: Nidec Copal; INSTANCENAME: INS469431
U? = WAKU_DEF100_1: SAVECOUNT: 1; UPDATEUSER: sptcae09; UPDATETIME: 10:40:02; PLOTTIME: HH:MM; TIME: 09:49:24; SAVEAREA0: -63393,-16950,474261,314592; ORIGINALSYMBOLORIGIN: (0,0); PAGENUMBER: 8; DESIGNED: TOSHIBA; SHTSAVECOUNT: 36; INSTANCENAME: INS636826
